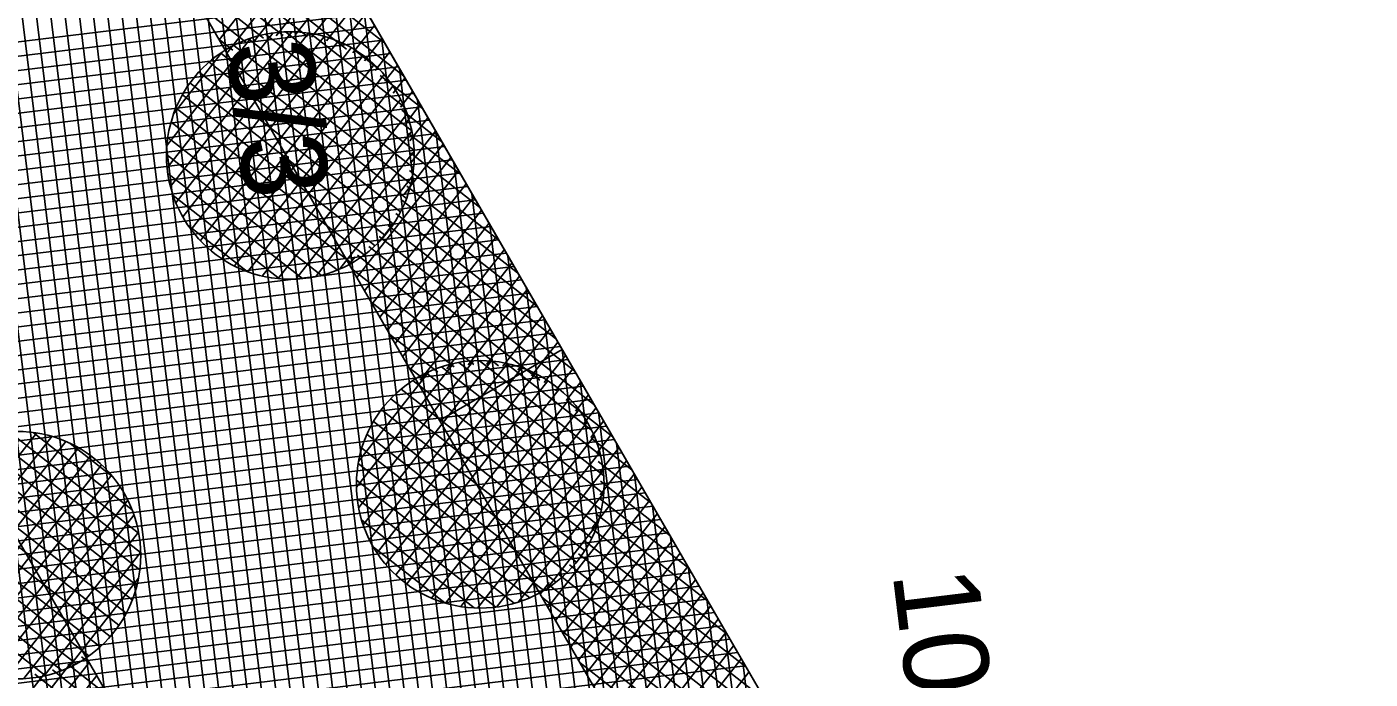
# Model space of a CAD drawing. Extents: x -566982 to -566809, y -1095912 to -1095685.
# Drawn here: x -566932.6 to -566913.62, y -1095755.62 to -1095746.4 of the extents above; entities that cross this region are included whole.
import ezdxf

# ---------------------------------------------------------------- set-up
doc = ezdxf.new("R2010")
doc.units = 0
for name, color, linetype in [('Vrstva 1', 7, 'Continuous'), ('Vrstva 40', 7, 'Continuous'), ('Vrstva 41', 7, 'Continuous'), ('Vrstva 42', 7, 'Continuous'), ('Vrstva 43', 7, 'Continuous'), ('Vrstva 44', 7, 'Continuous')]:
    doc.layers.add(name, color=color, linetype=linetype)

msp = doc.modelspace()

# ---------------------------------------------------------------- linework, layer by layer
at = {"layer": 'Vrstva 1'}
msp.add_line((-566945.07, -1095716.34), (-566890.01, -1095811.47), dxfattribs=at)
at = {"layer": 'Vrstva 41'}
for p, q in [((-566930.24, -1095744.513), (-566927.542, -1095746.624)), ((-566930.536, -1095744.789), (-566928.078, -1095746.713)), ((-566930.378, -1095744.659), (-566927.273, -1095747.089)), ((-566930.715, -1095744.903), (-566928.632, -1095746.533)), ((-566928.549, -1095744.884), (-566929.877, -1095746.582)), ((-566930.691, -1095745.176), (-566928.975, -1095746.519)), ((-566928.441, -1095745.071), (-566929.769, -1095746.768)), ((-566928.333, -1095745.257), (-566929.377, -1095746.592)), ((-566928.225, -1095745.444), (-566929.071, -1095746.525)), ((-566930.422, -1095745.64), (-566929.251, -1095746.557)), ((-566928.117, -1095745.631), (-566928.811, -1095746.517)), ((-566928.009, -1095745.817), (-566928.575, -1095746.541)), ((-566930.154, -1095746.104), (-566929.483, -1095746.629)), ((-566927.901, -1095746.004), (-566928.362, -1095746.593)), ((-566927.793, -1095746.19), (-566928.168, -1095746.669)), ((-566927.685, -1095746.377), (-566927.988, -1095746.764)), ((-566929.885, -1095746.569), (-566929.687, -1095746.724)), ((-566927.577, -1095746.563), (-566927.824, -1095746.879)), ((-566927.469, -1095746.75), (-566927.674, -1095747.012)), ((-566927.606, -1095747.082), (-566927.004, -1095747.553)), ((-566927.361, -1095746.936), (-566927.538, -1095747.163)), ((-566927.253, -1095747.123), (-566927.418, -1095747.334)), ((-566927.145, -1095747.31), (-566927.318, -1095747.53)), ((-566927.037, -1095747.496), (-566927.238, -1095747.753)), ((-566927.299, -1095747.576), (-566926.736, -1095748.017)), ((-566926.929, -1095747.683), (-566927.184, -1095748.008)), ((-566926.821, -1095747.869), (-566927.177, -1095748.323)), ((-566926.713, -1095748.056), (-566927.262, -1095748.757)), ((-566927.202, -1095747.906), (-566926.467, -1095748.481)), ((-566926.605, -1095748.242), (-566927.934, -1095749.94)), ((-566927.172, -1095748.183), (-566926.198, -1095748.945)), ((-566926.497, -1095748.429), (-566927.826, -1095750.126)), ((-566927.187, -1095748.426), (-566925.93, -1095749.409)), ((-566926.389, -1095748.615), (-566927.718, -1095750.313)), ((-566926.281, -1095748.802), (-566927.61, -1095750.5)), ((-566927.229, -1095748.647), (-566925.661, -1095749.874)), ((-566926.173, -1095748.988), (-566927.502, -1095750.686)), ((-566927.296, -1095748.848), (-566925.393, -1095750.338)), ((-566927.49, -1095749.205), (-566924.855, -1095751.266)), ((-566926.066, -1095749.175), (-566927.394, -1095750.873)), ((-566927.383, -1095749.034), (-566925.124, -1095750.802)), ((-566927.617, -1095749.359), (-566924.587, -1095751.73)), ((-566925.958, -1095749.362), (-566927.286, -1095751.059)), ((-566927.762, -1095749.5), (-566925.347, -1095751.389)), ((-566925.85, -1095749.548), (-566927.178, -1095751.246)), ((-566927.959, -1095749.648), (-566928.042, -1095749.753)), ((-566927.926, -1095749.625), (-566925.93, -1095751.187)), ((-566925.742, -1095749.735), (-566927.039, -1095751.393)), ((-566928.004, -1095749.818), (-566926.278, -1095751.168)), ((-566925.634, -1095749.921), (-566926.66, -1095751.233)), ((-566925.526, -1095750.108), (-566926.36, -1095751.174)), ((-566927.736, -1095750.282), (-566926.556, -1095751.205)), ((-566925.418, -1095750.294), (-566926.102, -1095751.169)), ((-566925.31, -1095750.481), (-566925.869, -1095751.195)), ((-566925.202, -1095750.667), (-566925.658, -1095751.251)), ((-566927.467, -1095750.746), (-566926.79, -1095751.276)), ((-566925.094, -1095750.854), (-566925.465, -1095751.329)), ((-566924.986, -1095751.041), (-566925.288, -1095751.426)), ((-566927.198, -1095751.21), (-566926.995, -1095751.369)), ((-566924.878, -1095751.227), (-566925.124, -1095751.542)), ((-566924.77, -1095751.414), (-566924.976, -1095751.677)), ((-566924.662, -1095751.6), (-566924.842, -1095751.83)), ((-566924.962, -1095751.69), (-566924.318, -1095752.194)), ((-566924.554, -1095751.787), (-566924.724, -1095752.005)), ((-566924.446, -1095751.973), (-566924.626, -1095752.204)), ((-566924.624, -1095752.209), (-566924.049, -1095752.659)), ((-566924.338, -1095752.16), (-566924.549, -1095752.43)), ((-566924.23, -1095752.346), (-566924.5, -1095752.692)), ((-566924.524, -1095752.541), (-566923.781, -1095753.123)), ((-566924.122, -1095752.533), (-566924.497, -1095753.012)), ((-566924.014, -1095752.72), (-566924.607, -1095753.478)), ((-566923.906, -1095752.906), (-566925.234, -1095754.604)), ((-566924.491, -1095752.821), (-566923.512, -1095753.587)), ((-566923.798, -1095753.093), (-566925.126, -1095754.79)), ((-566924.504, -1095753.064), (-566923.243, -1095754.051)), ((-566923.69, -1095753.279), (-566925.018, -1095754.977)), ((-566924.546, -1095753.286), (-566922.975, -1095754.515)), ((-566923.582, -1095753.466), (-566924.91, -1095755.163)), ((-566924.611, -1095753.489), (-566922.706, -1095754.979)), ((-566923.474, -1095753.652), (-566924.802, -1095755.35)), ((-566924.697, -1095753.675), (-566922.437, -1095755.444)), ((-566924.803, -1095753.846), (-566922.169, -1095755.908)), ((-566923.366, -1095753.839), (-566924.694, -1095755.536)), ((-566925.073, -1095754.143), (-566921.631, -1095756.836)), ((-566924.929, -1095754.002), (-566921.9, -1095756.372)), ((-566923.258, -1095754.025), (-566924.586, -1095755.723)), ((-566925.214, -1095754.253), (-566925.342, -1095754.417)), ((-566925.237, -1095754.269), (-566922.857, -1095756.131)), ((-566923.15, -1095754.212), (-566924.478, -1095755.91)), ((-566925.318, -1095754.46), (-566923.271, -1095756.061)), ((-566923.042, -1095754.399), (-566924.37, -1095756.096)), ((-566922.934, -1095754.585), (-566924.263, -1095756.283)), ((-566922.826, -1095754.772), (-566923.902, -1095756.146)), ((-566925.049, -1095754.924), (-566923.581, -1095756.072)), ((-566922.718, -1095754.958), (-566923.591, -1095756.074)), ((-566922.61, -1095755.145), (-566923.326, -1095756.059)), ((-566931.972, -1095755.383), (-566933.154, -1095756.893)), ((-566931.717, -1095755.382), (-566933.046, -1095757.079)), ((-566932.015, -1095755.406), (-566931.445, -1095755.852)), ((-566931.826, -1095755.3), (-566931.714, -1095755.387)), ((-566924.78, -1095755.388), (-566923.835, -1095756.128)), ((-566922.502, -1095755.331), (-566923.088, -1095756.079)), ((-566932.33, -1095755.516), (-566933.262, -1095756.706)), ((-566931.609, -1095755.568), (-566932.938, -1095757.266)), ((-566932.485, -1095755.546), (-566930.908, -1095756.78)), ((-566932.234, -1095755.488), (-566931.177, -1095756.316)), ((-566922.394, -1095755.518), (-566922.871, -1095756.128))]:
    msp.add_line(p, q, dxfattribs=at)
at = {"layer": 'Vrstva 42'}
msp.add_line((-566925.033, -1095750.959), (-566926.764, -1095751.961), dxfattribs=at)
for points in [[(-566834.15, -1095760.69), (-566836.072, -1095760.136), (-566841.286, -1095779.189), (-566855.268, -1095796.126), (-566881.984, -1095814.851), (-566891.818, -1095824.318), (-566954.342, -1095716.292), (-566956.66, -1095716.28), (-566892.27, -1095827.53), (-566880.71, -1095816.4), (-566853.9, -1095797.61), (-566839.47, -1095780.13)], [(-566945.07, -1095716.34), (-566947.388, -1095716.328), (-566890.462, -1095814.681), (-566885.816, -1095810.21), (-566859.382, -1095791.684), (-566846.734, -1095776.361), (-566841.831, -1095758.448), (-566843.76, -1095757.92), (-566848.55, -1095775.42), (-566860.75, -1095790.2), (-566887.09, -1095808.66), (-566890.01, -1095811.47)]]:
    msp.add_lwpolyline(points, close=True, dxfattribs=at)
at = {"layer": 'Vrstva 43'}
for p, q in [((-566935.245, -1095733.316), (-566932.157, -1095758.614)), ((-566934.989, -1095733.757), (-566931.902, -1095759.055)), ((-566934.734, -1095734.198), (-566931.647, -1095759.497)), ((-566934.479, -1095734.639), (-566931.392, -1095759.938)), ((-566934.223, -1095735.08), (-566931.136, -1095760.379)), ((-566933.968, -1095735.521), (-566930.881, -1095760.82)), ((-566933.713, -1095735.962), (-566930.626, -1095761.261)), ((-566933.457, -1095736.404), (-566930.37, -1095761.702)), ((-566933.202, -1095736.845), (-566930.115, -1095762.143)), ((-566932.947, -1095737.286), (-566929.86, -1095762.584)), ((-566932.692, -1095737.727), (-566929.604, -1095763.026)), ((-566932.436, -1095738.168), (-566929.349, -1095763.467)), ((-566932.181, -1095738.609), (-566929.094, -1095763.908)), ((-566931.926, -1095739.05), (-566928.838, -1095764.349)), ((-566931.67, -1095739.491), (-566928.583, -1095764.79)), ((-566931.415, -1095739.933), (-566928.328, -1095765.231)), ((-566931.16, -1095740.374), (-566928.072, -1095765.672)), ((-566930.904, -1095740.815), (-566927.817, -1095766.113)), ((-566930.649, -1095741.256), (-566927.562, -1095766.554)), ((-566930.394, -1095741.697), (-566927.306, -1095766.996)), ((-566930.138, -1095742.138), (-566927.051, -1095767.437)), ((-566929.883, -1095742.579), (-566926.796, -1095767.878)), ((-566929.628, -1095743.02), (-566926.541, -1095768.319)), ((-566929.372, -1095743.461), (-566926.285, -1095768.76)), ((-566929.117, -1095743.903), (-566926.03, -1095769.201)), ((-566928.862, -1095744.344), (-566925.775, -1095769.642)), ((-566928.607, -1095744.785), (-566925.519, -1095770.083)), ((-566928.351, -1095745.226), (-566925.264, -1095770.525)), ((-566928.096, -1095745.667), (-566925.009, -1095770.966)), ((-566938.684, -1095747.337), (-566927.892, -1095746.02)), ((-566927.841, -1095746.108), (-566924.753, -1095771.407)), ((-566938.576, -1095747.525), (-566927.783, -1095746.208)), ((-566938.467, -1095747.714), (-566927.674, -1095746.397)), ((-566927.585, -1095746.549), (-566924.498, -1095771.848)), ((-566938.358, -1095747.902), (-566927.565, -1095746.585)), ((-566938.249, -1095748.09), (-566927.456, -1095746.773)), ((-566938.14, -1095748.278), (-566927.347, -1095746.961)), ((-566927.33, -1095746.99), (-566924.243, -1095772.289)), ((-566938.031, -1095748.466), (-566927.238, -1095747.149)), ((-566937.922, -1095748.655), (-566927.129, -1095747.338)), ((-566927.075, -1095747.432), (-566923.987, -1095772.73)), ((-566937.813, -1095748.843), (-566927.02, -1095747.526)), ((-566937.704, -1095749.031), (-566926.911, -1095747.714)), ((-566926.819, -1095747.873), (-566923.732, -1095773.171)), ((-566937.595, -1095749.219), (-566926.802, -1095747.902)), ((-566937.486, -1095749.407), (-566926.693, -1095748.09)), ((-566937.377, -1095749.596), (-566926.584, -1095748.278)), ((-566926.564, -1095748.314), (-566923.477, -1095773.612)), ((-566937.268, -1095749.784), (-566926.476, -1095748.467)), ((-566937.16, -1095749.972), (-566926.367, -1095748.655)), ((-566926.309, -1095748.755), (-566923.221, -1095774.054)), ((-566937.051, -1095750.16), (-566926.258, -1095748.843)), ((-566936.942, -1095750.348), (-566926.149, -1095749.031)), ((-566926.053, -1095749.196), (-566922.966, -1095774.495)), ((-566936.833, -1095750.536), (-566926.04, -1095749.219)), ((-566936.724, -1095750.725), (-566925.931, -1095749.408)), ((-566936.615, -1095750.913), (-566925.822, -1095749.596)), ((-566925.798, -1095749.637), (-566922.711, -1095774.936)), ((-566936.506, -1095751.101), (-566925.713, -1095749.784)), ((-566936.397, -1095751.289), (-566925.604, -1095749.972)), ((-566925.543, -1095750.078), (-566922.456, -1095775.377)), ((-566936.288, -1095751.477), (-566925.495, -1095750.16)), ((-566936.179, -1095751.666), (-566925.386, -1095750.349)), ((-566936.07, -1095751.854), (-566925.277, -1095750.537)), ((-566925.287, -1095750.519), (-566922.2, -1095775.818)), ((-566935.961, -1095752.042), (-566925.168, -1095750.725)), ((-566935.852, -1095752.23), (-566925.06, -1095750.913)), ((-566935.744, -1095752.418), (-566924.951, -1095751.101)), ((-566925.032, -1095750.96), (-566921.945, -1095776.259)), ((-566935.635, -1095752.607), (-566924.842, -1095751.29)), ((-566935.526, -1095752.795), (-566924.733, -1095751.478)), ((-566924.777, -1095751.402), (-566921.69, -1095776.7)), ((-566935.417, -1095752.983), (-566924.624, -1095751.666)), ((-566935.308, -1095753.171), (-566924.515, -1095751.854)), ((-566924.521, -1095751.843), (-566921.434, -1095777.141)), ((-566935.199, -1095753.359), (-566924.406, -1095752.042)), ((-566935.09, -1095753.548), (-566924.297, -1095752.23)), ((-566934.981, -1095753.736), (-566924.188, -1095752.419)), ((-566924.266, -1095752.284), (-566921.179, -1095777.582)), ((-566934.872, -1095753.924), (-566924.079, -1095752.607)), ((-566934.763, -1095754.112), (-566923.97, -1095752.795)), ((-566924.011, -1095752.725), (-566920.924, -1095778.024)), ((-566934.654, -1095754.3), (-566923.861, -1095752.983)), ((-566934.545, -1095754.489), (-566923.752, -1095753.171)), ((-566923.756, -1095753.166), (-566920.668, -1095778.465)), ((-566934.436, -1095754.677), (-566923.644, -1095753.36)), ((-566934.328, -1095754.865), (-566923.535, -1095753.548)), ((-566934.219, -1095755.053), (-566923.426, -1095753.736)), ((-566923.5, -1095753.607), (-566920.413, -1095778.906)), ((-566934.11, -1095755.241), (-566923.317, -1095753.924)), ((-566934.001, -1095755.429), (-566923.208, -1095754.112)), ((-566923.245, -1095754.048), (-566920.158, -1095779.347)), ((-566933.892, -1095755.618), (-566923.099, -1095754.301)), ((-566933.783, -1095755.806), (-566922.99, -1095754.489)), ((-566922.99, -1095754.489), (-566919.902, -1095779.788)), ((-566933.674, -1095755.994), (-566922.881, -1095754.677)), ((-566933.565, -1095756.182), (-566922.772, -1095754.865)), ((-566933.456, -1095756.37), (-566922.663, -1095755.053)), ((-566922.734, -1095754.931), (-566919.647, -1095780.229)), ((-566933.347, -1095756.559), (-566922.554, -1095755.242)), ((-566933.238, -1095756.747), (-566922.445, -1095755.43)), ((-566922.479, -1095755.372), (-566919.392, -1095780.67))]:
    msp.add_line(p, q, dxfattribs=at)
msp.add_lwpolyline([(-566834.15, -1095760.69), (-566843.76, -1095757.92), (-566848.55, -1095775.42), (-566860.75, -1095790.2), (-566887.09, -1095808.66), (-566890.01, -1095811.47), (-566945.07, -1095716.34), (-566956.66, -1095716.28), (-566892.27, -1095827.53), (-566880.71, -1095816.4), (-566853.9, -1095797.61), (-566839.47, -1095780.13)], close=True, dxfattribs=at)
at = {"layer": 'Vrstva 44'}
for p, q in [((-566929.121, -1095746.485), (-566930.612, -1095748.39)), ((-566928.852, -1095746.466), (-566930.565, -1095748.655)), ((-566928.614, -1095746.486), (-566930.489, -1095748.882)), ((-566928.397, -1095746.533), (-566930.393, -1095749.083)), ((-566929.222, -1095746.502), (-566927.126, -1095748.142)), ((-566928.94, -1095746.468), (-566927.16, -1095747.861)), ((-566928.587, -1095746.491), (-566927.265, -1095747.525)), ((-566929.434, -1095746.56), (-566930.615, -1095748.07)), ((-566928.196, -1095746.601), (-566930.276, -1095749.259)), ((-566928.014, -1095746.692), (-566930.144, -1095749.415)), ((-566929.671, -1095746.658), (-566927.171, -1095748.615)), ((-566929.461, -1095746.569), (-566927.133, -1095748.39)), ((-566927.976, -1095746.715), (-566927.626, -1095746.988)), ((-566929.847, -1095746.764), (-566930.519, -1095747.622)), ((-566930.018, -1095746.895), (-566927.315, -1095749.01)), ((-566927.845, -1095746.801), (-566929.998, -1095749.553)), ((-566929.854, -1095746.769), (-566927.231, -1095748.821)), ((-566927.69, -1095746.928), (-566929.839, -1095749.674)), ((-566930.163, -1095747.035), (-566927.418, -1095749.183)), ((-566927.549, -1095747.072), (-566929.664, -1095749.775)), ((-566930.291, -1095747.189), (-566927.538, -1095749.343)), ((-566927.423, -1095747.236), (-566929.474, -1095749.857)), ((-566930.398, -1095747.359), (-566927.675, -1095749.49)), ((-566927.315, -1095747.422), (-566929.269, -1095749.919)), ((-566930.487, -1095747.544), (-566927.832, -1095749.621)), ((-566927.225, -1095747.631), (-566929.043, -1095749.955)), ((-566930.556, -1095747.743), (-566928.01, -1095749.736)), ((-566927.158, -1095747.871), (-566928.795, -1095749.962)), ((-566930.604, -1095747.96), (-566928.21, -1095749.833)), ((-566930.621, -1095748.201), (-566928.437, -1095749.909)), ((-566927.125, -1095748.153), (-566928.512, -1095749.926)), ((-566930.604, -1095748.468), (-566928.703, -1095749.955)), ((-566927.147, -1095748.506), (-566928.173, -1095749.817)), ((-566930.529, -1095748.78), (-566929.026, -1095749.957)), ((-566930.319, -1095749.199), (-566929.481, -1095749.854)), ((-566927.379, -1095749.127), (-566927.619, -1095749.434)), ((-566926.571, -1095751.158), (-566927.938, -1095752.906)), ((-566926.915, -1095751.274), (-566927.908, -1095752.543)), ((-566926.286, -1095751.119), (-566927.907, -1095753.191)), ((-566926.035, -1095751.123), (-566927.844, -1095753.435)), ((-566925.809, -1095751.158), (-566927.754, -1095753.644)), ((-566925.602, -1095751.218), (-566927.647, -1095753.831)), ((-566926.951, -1095751.29), (-566924.479, -1095753.224)), ((-566926.736, -1095751.204), (-566924.445, -1095752.996)), ((-566926.492, -1095751.141), (-566924.446, -1095752.741)), ((-566926.199, -1095751.116), (-566924.49, -1095752.453)), ((-566925.828, -1095751.153), (-566924.619, -1095752.099)), ((-566925.411, -1095751.299), (-566927.523, -1095753.998)), ((-566925.235, -1095751.399), (-566927.383, -1095754.143)), ((-566927.14, -1095751.396), (-566924.536, -1095753.433)), ((-566927.454, -1095751.657), (-566924.714, -1095753.802)), ((-566927.306, -1095751.519), (-566924.614, -1095753.626)), ((-566925.074, -1095751.517), (-566927.229, -1095754.271)), ((-566924.928, -1095751.655), (-566927.061, -1095754.38)), ((-566927.585, -1095751.809), (-566924.831, -1095753.964)), ((-566924.796, -1095751.81), (-566926.878, -1095754.472)), ((-566927.697, -1095751.975), (-566924.966, -1095754.112)), ((-566924.679, -1095751.985), (-566926.681, -1095754.544)), ((-566932.46, -1095752.139), (-566934.346, -1095754.549)), ((-566932.244, -1095752.187), (-566934.247, -1095754.748)), ((-566933.357, -1095752.229), (-566931.001, -1095754.072)), ((-566933.121, -1095752.16), (-566930.988, -1095753.829)), ((-566932.848, -1095752.12), (-566931.017, -1095753.552)), ((-566932.508, -1095752.131), (-566931.11, -1095753.225)), ((-566927.789, -1095752.157), (-566925.119, -1095754.247)), ((-566924.579, -1095752.183), (-566926.464, -1095754.591)), ((-566932.045, -1095752.258), (-566934.13, -1095754.922)), ((-566931.864, -1095752.35), (-566933.997, -1095755.077)), ((-566933.743, -1095752.435), (-566931.107, -1095754.498)), ((-566933.561, -1095752.323), (-566931.042, -1095754.295)), ((-566931.984, -1095752.287), (-566931.383, -1095752.758)), ((-566927.862, -1095752.354), (-566925.292, -1095754.366)), ((-566924.502, -1095752.409), (-566926.227, -1095754.614)), ((-566933.904, -1095752.563), (-566931.193, -1095754.684)), ((-566931.696, -1095752.461), (-566933.85, -1095755.214)), ((-566931.542, -1095752.589), (-566933.689, -1095755.333)), ((-566927.913, -1095752.568), (-566925.488, -1095754.466)), ((-566934.047, -1095752.705), (-566931.297, -1095754.856)), ((-566931.402, -1095752.734), (-566933.513, -1095755.432)), ((-566927.938, -1095752.803), (-566925.71, -1095754.546)), ((-566924.452, -1095752.669), (-566925.961, -1095754.598)), ((-566934.17, -1095752.863), (-566931.42, -1095755.015)), ((-566931.278, -1095752.9), (-566933.322, -1095755.512)), ((-566924.444, -1095752.984), (-566925.652, -1095754.528)), ((-566934.275, -1095753.034), (-566931.559, -1095755.159)), ((-566931.171, -1095753.088), (-566933.116, -1095755.573)), ((-566927.927, -1095753.065), (-566925.968, -1095754.598)), ((-566934.362, -1095753.22), (-566931.72, -1095755.287)), ((-566931.082, -1095753.299), (-566932.888, -1095755.606)), ((-566927.864, -1095753.369), (-566926.276, -1095754.611)), ((-566934.429, -1095753.422), (-566931.901, -1095755.4)), ((-566931.019, -1095753.542), (-566932.638, -1095755.611)), ((-566924.533, -1095753.422), (-566925.251, -1095754.34)), ((-566934.471, -1095753.642), (-566932.104, -1095755.495)), ((-566927.696, -1095753.754), (-566926.69, -1095754.541)), ((-566934.485, -1095753.886), (-566932.337, -1095755.567)), ((-566930.988, -1095753.827), (-566932.351, -1095755.57)), ((-566931.019, -1095754.192), (-566932.006, -1095755.454))]:
    msp.add_line(p, q, dxfattribs=at)
for centre in [(-566928.873, -1095748.215), (-566926.19, -1095752.864), (-566932.737, -1095753.865)]:
    msp.add_circle(centre, 1.75, dxfattribs=at)

# ---------------------------------------------------------------- texts
at = {"layer": 'Vrstva 40'}
for s, p in [('3/3', (-566929.769, -1095746.652)), ('10/40', (-566920.365, -1095754.118))]:
    msp.add_text(s, height=1.2, rotation=276.9575, dxfattribs=at).set_placement(p)

doc.saveas('drawing.dxf')
